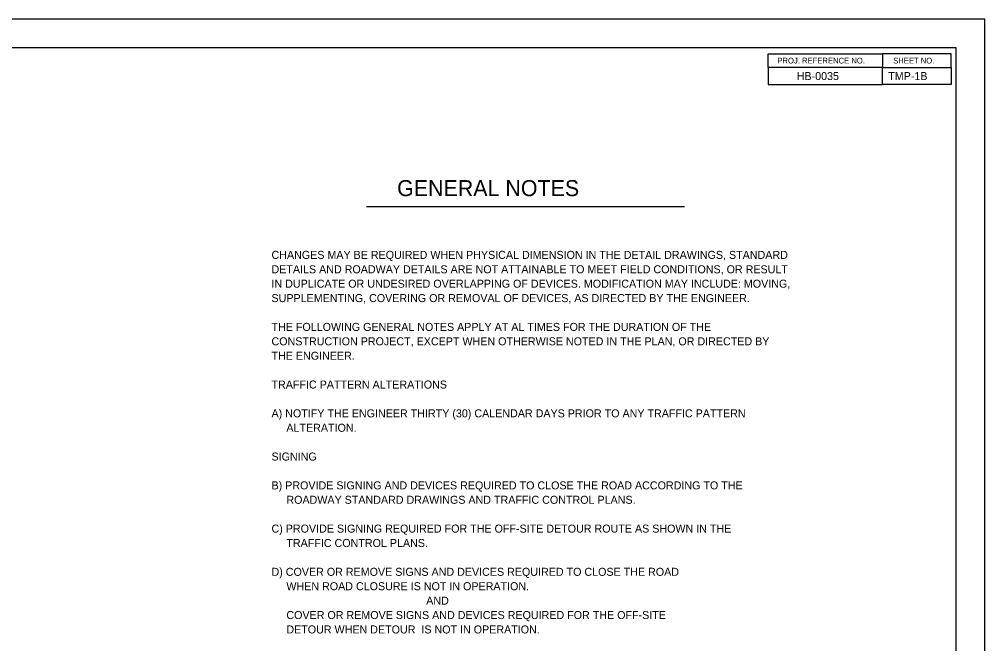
# Model space of a CAD drawing. Extents: x -38542 to 45858, y -25814 to 29186.
# Drawn here: x 1012 to 1856, y -74 to 472 of the extents above; entities that cross this region are included whole.
import ezdxf

# ---------------------------------------------------------------- set-up
doc = ezdxf.new("R2010")
doc.units = 0
for name, color, linetype in [('Exist Road Non-System Type 51 Label', 7, 'Continuous'), ('Sheet Plan CELL', 7, 'Continuous'), ('Sheet Plot Border Outside CELL', 7, 'Continuous'), ('WZ RC1000 CELL', 7, 'Continuous')]:
    doc.layers.add(name, color=color, linetype=linetype)

msp = doc.modelspace()

# ---------------------------------------------------------------- linework, layer by layer
at = {"layer": 'Exist Road Non-System Type 51 Label'}
msp.add_line((1766.61, 429.5), (1826.61, 429.5), dxfattribs=at)
for points in [[(1830.96, 446.64), (330.96, 446.64), (330.96, -603.36), (1830.96, -603.36)], [(1666.61, 441.5), (1766.61, 441.5), (1766.61, 429.5), (1666.61, 429.5)], [(1766.61, 429.5), (1826.61, 429.5), (1826.61, 441.5), (1766.61, 441.5)], [(1766.61, 429.5), (1666.61, 429.5), (1666.61, 414.5), (1766.61, 414.5)], [(1766.61, 429.5), (1826.61, 429.5), (1826.61, 414.5), (1766.61, 414.5)]]:
    msp.add_lwpolyline(points, close=True, dxfattribs=at)
at = {"layer": 'Sheet Plot Border Outside CELL'}
msp.add_lwpolyline([(167.97, -628.36), (1855.96, -628.36), (1855.96, 471.64), (167.97, 471.64)], close=True, dxfattribs=at)
at = {"layer": 'WZ RC1000 CELL'}
msp.add_line((1315.46, 307.82), (1593.41, 307.82), dxfattribs=at)

# ---------------------------------------------------------------- texts
at = {"layer": 'Exist Road Non-System Type 51 Label'}
for s, height, p in [('PROJ. REFERENCE NO.', 4.9992, (1674.72, 433)), ('SHEET NO.', 4.999, (1775.94, 433))]:
    msp.add_text(s, height=height, rotation=0.00056, dxfattribs=at).set_placement(p)
for s, height, p in [('HB-0035', 7, (1691.61, 418.5)), ('TMP-1B  ', 7, (1771.61, 418.5)), ('GENERAL NOTES', 14, (1342.26, 316.98))]:
    msp.add_text(s, height=height, dxfattribs=at).set_placement(p)
at = {"layer": 'Sheet Plan CELL'}
for s, p in [('CHANGES MAY BE REQUIRED WHEN PHYSICAL DIMENSION IN THE DETAIL DRAWINGS, STANDARD', (1232.45, 262.11)), ('DETAILS AND ROADWAY DETAILS ARE NOT ATTAINABLE TO MEET FIELD CONDITIONS, OR RESULT ', (1232.45, 249.51)), ('IN DUPLICATE OR UNDESIRED OVERLAPPING OF DEVICES. MODIFICATION MAY INCLUDE: MOVING,', (1232.45, 236.91)), ('SUPPLEMENTING, COVERING OR REMOVAL OF DEVICES, AS DIRECTED BY THE ENGINEER. ', (1232.45, 224.31)), ('THE FOLLOWING GENERAL NOTES APPLY AT AL TIMES FOR THE DURATION OF THE ', (1232.45, 199.11)), ('CONSTRUCTION PROJECT, EXCEPT WHEN OTHERWISE NOTED IN THE PLAN, OR DIRECTED BY ', (1232.45, 186.51)), ('THE ENGINEER.', (1232.45, 173.91)), ('TRAFFIC PATTERN ALTERATIONS', (1232.45, 148.71)), ('A) NOTIFY THE ENGINEER THIRTY (30) CALENDAR DAYS PRIOR TO ANY TRAFFIC PATTERN ', (1232.45, 123.51)), ('     ALTERATION.', (1232.45, 110.91)), ('SIGNING', (1232.45, 85.71)), ('B) PROVIDE SIGNING AND DEVICES REQUIRED TO CLOSE THE ROAD ACCORDING TO THE ', (1232.45, 60.51)), ('     ROADWAY STANDARD DRAWINGS AND TRAFFIC CONTROL PLANS.', (1232.45, 47.91)), ('C) PROVIDE SIGNING REQUIRED FOR THE OFF-SITE DETOUR ROUTE AS SHOWN IN THE ', (1232.45, 22.71)), ('     TRAFFIC CONTROL PLANS. ', (1232.45, 10.11)), ('D) COVER OR REMOVE SIGNS AND DEVICES REQUIRED TO CLOSE THE ROAD ', (1232.45, -15.09)), ('     WHEN ROAD CLOSURE IS NOT IN OPERATION. ', (1232.45, -27.69)), ('                                                    AND', (1232.45, -40.29)), ('     COVER OR REMOVE SIGNS AND DEVICES REQUIRED FOR THE OFF-SITE  ', (1232.45, -52.89)), ('     DETOUR WHEN DETOUR  IS NOT IN OPERATION.', (1232.45, -65.49))]:
    msp.add_text(s, height=7, rotation=0, dxfattribs=at).set_placement(p)

doc.saveas('drawing.dxf')
